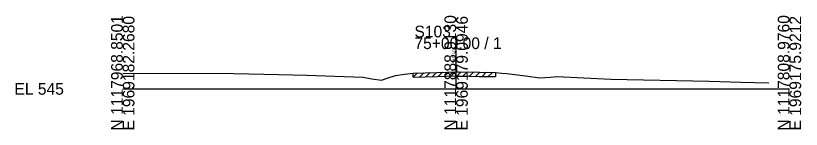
# Model space of a CAD drawing. Extents: x -26 to 163, y -10 to 45020.
# Drawn here: x -25.7 to 162.8, y 33990.3 to 34017.5 of the extents above; entities that cross this region are included whole.
import ezdxf

# ---------------------------------------------------------------- set-up
doc = ezdxf.new("R2010")
doc.units = 0
for name, color, linetype in [('RD_GPK_XS_Cell', 7, 'Continuous'), ('RD_XS_ExGround', 7, 'Continuous'), ('RD_XS_ExPaveRet', 7, 'Continuous'), ('RD_XS_TX_Elev_EX', 7, 'Continuous')]:
    doc.layers.add(name, color=color, linetype=linetype)

msp = doc.modelspace()

# ---------------------------------------------------------------- linework, layer by layer
at = {"layer": 'RD_GPK_XS_Cell'}
for p, q in [((80, 34000), (80, 34012.35)), ((0, 34000), (80, 34000)), ((80, 34000), (160, 34000))]:
    msp.add_line(p, q, dxfattribs=at)
at = {"layer": 'RD_XS_ExGround'}
for p, q in [((0, 34003.79), (26.63, 34003.65)), ((67.61, 34003.5), (69.73, 34003.78)), ((69.73, 34003.78), (75.43, 34003.96)), ((75.43, 34003.96), (80, 34004.1)), ((80, 34004.1), (80.6, 34004.12)), ((80.6, 34004.12), (85.57, 34004)), ((85.57, 34004), (89.48, 34003.93)), ((89.48, 34003.93), (90.99, 34003.8)), ((90.99, 34003.8), (92.15, 34003.72)), ((26.63, 34003.65), (37.42, 34003.46)), ((37.42, 34003.46), (44.1, 34003.25)), ((44.1, 34003.25), (57.7, 34002.83)), ((57.7, 34002.83), (59.76, 34002.44)), ((59.76, 34002.44), (62.07, 34002.06)), ((62.07, 34002.06), (63.67, 34002.63)), ((63.67, 34002.63), (65.46, 34003.2)), ((65.46, 34003.2), (67.61, 34003.5)), ((92.15, 34003.72), (96.64, 34003.13)), ((96.64, 34003.13), (100.12, 34002.66)), ((100.12, 34002.66), (102.64, 34002.84)), ((102.64, 34002.84), (104.18, 34003)), ((104.18, 34003), (117.1, 34002.34)), ((117.1, 34002.34), (140.73, 34001.84)), ((140.73, 34001.84), (148.37, 34001.6)), ((148.37, 34001.6), (155.09, 34001.43))]:
    msp.add_line(p, q, dxfattribs=at)
at = {"layer": 'RD_XS_ExPaveRet'}
for p, q in [((69.73, 34002.78), (70.77, 34003.81)), ((69.73, 34002.78), (69.73, 34003.78)), ((71.23, 34002.83), (72.27, 34003.86)), ((72.73, 34002.87), (73.77, 34003.91)), ((74.23, 34002.92), (75.27, 34003.95)), ((75.73, 34002.97), (76.77, 34004)), ((77.23, 34003.01), (78.27, 34004.04)), ((78.73, 34003.06), (79.77, 34004.09)), ((80.23, 34003.11), (81.23, 34004.1)), ((81.73, 34003.09), (82.71, 34004.07)), ((83.23, 34003.06), (84.21, 34004.03)), ((84.73, 34003.02), (85.71, 34004)), ((86.23, 34002.99), (87.22, 34003.97)), ((87.73, 34002.96), (88.72, 34003.94)), ((89.48, 34003.93), (89.48, 34002.93)), ((69.73, 34002.78), (75.43, 34002.96)), ((75.43, 34002.96), (80, 34003.1)), ((80, 34003.1), (80.6, 34003.12)), ((80.6, 34003.12), (85.57, 34003)), ((85.57, 34003), (89.48, 34002.93))]:
    msp.add_line(p, q, dxfattribs=at)

# ---------------------------------------------------------------- texts
at = {"layer": 'RD_GPK_XS_Cell'}
for s, p in [('N 1117968.8501', (0, 33990)), ('E 1969182.2680', (2.8, 33990)), ('N 1117888.9130', (80, 33990)), ('E 1969179.0946', (82.8, 33990)), ('N 1117808.9760', (160, 33990)), ('E 1969175.9212', (162.8, 33990))]:
    msp.add_text(s, height=2.8, rotation=90, dxfattribs=at).set_placement(p)
for s, p in [('S103', (70, 34012.35)), ('75+00.00 / 1', (70, 34009.55)), ('EL 545', (-26, 33998.6))]:
    msp.add_text(s, height=2.8, dxfattribs=at).set_placement(p)
at = {"layer": 'RD_XS_TX_Elev_EX'}
msp.add_text('549.10', height=0.8, rotation=90, dxfattribs=at).set_placement((79.9, 34006.1))

doc.saveas('drawing.dxf')
